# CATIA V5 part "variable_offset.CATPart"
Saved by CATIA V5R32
Part number: Part1
Bounding box of the stored display mesh (mm): x -40 to 40, y -142.035 to 125.092, z -43.841 to 47.521
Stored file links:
  D:\PROJECTS\Project 2022\CATIA V5 6R 2022\Resources\Part Files\c17_catia_v6_6r2022_prt\variable_offset.CATPart
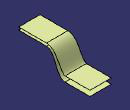
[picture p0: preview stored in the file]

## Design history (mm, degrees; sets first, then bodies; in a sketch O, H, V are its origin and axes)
Set1
  Sketch1 on yz-plane, origin (0, 0, 0), H (0, 1, 0), V (0, 0, 1)
    line L1 (-37.9526, 37.5213) -> (-142.0346, 37.5213)
    horizontal: L1 H
  Sketch2 on yz-plane, origin (0, 0, 0), H (0, 1, 0), V (0, 0, 1)
    line L1 (31.6324, -43.8406) -> (125.0922, -43.8406)
    horizontal: L1 H
  Extrude1: Element1 Sketch1, Lim1 40, Lim2 40
  Extrude2: Element1 Sketch2, Lim1 40, Lim2 40
  Blend1: StartLimit {blendlimit Curve edge of Extrude1, Support Extrude1}, EndLimit {blendlimit Curve edge of Extrude2, Support Extrude2}
  Join1: Elements (Extrude1; Blend1; Extrude2)
  GSOVariableOffset1: GlobalSurface Join1, ListOfConstraints Blend1
Body1 (main body)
